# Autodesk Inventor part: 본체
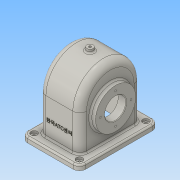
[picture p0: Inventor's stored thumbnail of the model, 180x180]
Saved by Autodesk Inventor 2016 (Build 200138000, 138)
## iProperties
Created: 2018-08
Part Number: 본체
Material: 알루미늄 6061
Document SubType Name: Modeling
Designer: Administrator
Density: 2.7 g/cm^3
Appearance: 강철
Mass: 1092.39 g
Surface Area: 1180.22 cm^2
Volume: 404.587 cm^3
Author: Administrator
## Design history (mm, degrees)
sketch "스케치1"
  geometry: L1 (-55, -75)-(55, -75); L2 (55, -75)-(55, 75); L3 (55, 75)-(-55, 75); L4 (-55, 75)-(-55, -75); L5 (-55, -75)-(55, 75); L6 (55, -75)-(-55, 75); 1 further point
  constraints: 12 end point, 2 midpoint, 2 parallel, 1 horizontal, 1 perpendicular
  dimensions: "d0" = 110 distance of L3.end L2.end; "d1" = 150 distance of L2.end L1.end
extrude "돌출1" new body sketch "스케치1" distance "d2" = 10; taper "d3" = 0 deg
sketch "스케치2"
  geometry: L1 (0, 0)-(-58, 0); L2 (-58, 0)-(-58, 78); L3 (-58, 78)-(0, 78); L4 (0, 78)-(0, 0); L5 (58, 78)-(0, 78); L6 (58, 0)-(58, 78); L7 (0, 0)-(58, 0); A1 r 58 centre (0, 78) between (58, 78) and (-58, 78)
  constraints: 14 end point, 2 parallel, 2 point on circle, 2 symmetric about line, 1 centre point, 1 coincident, 1 horizontal, 1 perpendicular
  dimensions: "d4" = 78 distance of L6.start L5.start; "d5" = 58 radius of A1
extrude "돌출2" join sketch "스케치2" stored distance "d6" = 77; taper "d7" = 0 deg
sketch "스케치3"
  geometry: L1 (0, 0)-(-52, 0); L2 (-52, 0)-(-52, 78); L3 (-52, 78)-(0, 78); L4 (0, 78)-(0, 0); L5 (52, 78)-(0, 78); L6 (52, 0)-(52, 78); L7 (0, 0)-(52, 0); L8 (58, 78)-(58, 10) reference; A1 r 58 centre (0, 78) between (58, 78) and (-58, 78) reference; A2 r 52 centre (0, 78) between (52, 78) and (-52, 78)
  constraints: 14 end point, 2 parallel, 2 point on circle, 1 centre point, 1 horizontal, 1 perpendicular, 1 symmetric about line
  dimensions: "d8" = 6 radial gap between concentric circles of A1 A2; "d9" = 52 radius of A2 (derived); "d10" = 6 distance between parallel lines of L8 L6
extrude "돌출3" cut sketch "스케치3" stored distance "d11" = 67; taper "d12" = 0 deg
sketch "스케치4"
  geometry: L1 (96.719, 65)-(-83.201, 65); L2 (-33.5, 0)-(33.5, 0) reference; L3 (-33.5, 65)-(-48.5, 65); L4 (-48.5, 65)-(-48.5, 103); L5 (-48.5, 103)-(-33.5, 103); L6 (-33.5, 103)-(-33.5, 65); L7 (-33.5, 130)-(-33.5, 78) reference; L8 (19.5, 65)-(19.5, 93); L9 (19.5, 93)-(33.5, 104.747); L10 (33.5, 104.747)-(38.5, 104.747); L11 (38.5, 78)-(38.5, 136) reference; L12 (38.5, 104.747)-(38.5, 103); L13 (38.5, 103)-(43.5, 103); L14 (43.5, 103)-(43.5, 65); L15 (43.5, 65)-(19.5, 65); 1 further point
  constraints: 24 end point, 5 point on line, 3 horizontal, 3 perpendicular, 2 collinear, 2 parallel, 1 vertical
  dimensions: "d13" = 65 distance between parallel lines of L2 L1; "d14" = 76 diameter of L5 L1; "d15" = 50 deg angle of L8 L9; "d16" = 5 distance of L9.end L10.end; "d17" = 56 diameter of L8.end L1; "d18" = 76 diameter of L13 L1; "d19" = 5 distance between parallel lines of L12 L14; "d20" = 87 distance between parallel lines of L4 L11; "d21" = 24 distance between parallel lines of L8 L14
revolve "회전1" sketch "스케치4" stored, may be unused: angle "d22" = 90 deg
sketch "스케치5"
  geometry: C1 r 38 at (0, 0) reference; C2 r 20 at (0, 0); 1 further point
  constraints: 1 centre point
  dimensions: "d23" = 40 diameter of C2
extrude "돌출4" cut sketch "스케치5" stored distance "d24" = 67; taper "d25" = 0 deg
sketch "스케치6" dims "d26" = 58
  geometry: L1 (0, 0)-(-29, 0); C1 r 38 at (0, 0) reference; 2 further points
  constraints: 2 end point, 1 coincident, 1 horizontal, 1 horizontal alignment, 2 other
hole "구멍1" sketch "스케치6" at (-29, 0) diameter "d27" = 3.242; stored, may be unused: countersink angle "d31" = 90 deg, drill point angle "d33" = 118 deg; dims "d28" = 8, "d29" = 4, "d30" = 2, "d32" = 10
node "작업 평면1"
sketch "스케치7"
  geometry: L1 (48.5, 38)-(48.5, -38) reference; L2 (-43.5, 1.621)-(-38.5, 1.621) reference; L3 (48.5, 1.621)-(48.5, -1.621) reference; L4 (-38.5, 58)-(-38.5, -58) reference; L5 (55, 75)-(-55, 75) reference; C1 r 6 at (0, 0); 1 further point
  constraints: 1 centre point
  dimensions: "d39" = 12 diameter of C1; "d103" = 38.5 distance from line of C1.centre L4; "d104" = 75 distance from line of L5 C1.centre
fillet "모깎기1" dims "d51" = 13
fillet "모깎기2" dims "d52" = 8
chamfer "모따기1" distance "d53" = 1; stored, may be unused: second distance "d54" = 2, angle "d55" = 45 deg
chamfer "모따기2" distance "d56" = 1; stored, may be unused: second distance "d57" = 2, angle "d58" = 45 deg
fillet "모깎기3" dims "d59" = 3
fillet "모깎기4" dims "d60" = 12
fillet "모깎기5" dims "d61" = 3
fillet "모깎기6" dims "d62" = 3
sketch "스케치8"
  geometry: L1 (-17.5, -78)-(68.5, -78) reference; L2 (-13, 0)-(-13, -65) reference; 2 further points
  constraints: 1 other
  dimensions: "d63" = 40 distance from line of L1 point (25.5, -38); "d64" = 38.5 distance from line of point (25.5, -38) L2
feature "엠보싱1" sketch "스케치8" dims "d0" = 110, "d1" = 150, "d4" = 78, "d65" = 0.5, "d66" = 0
hole "구멍3" diameter "d69" = 5; stored, may be unused: countersink angle "d73" = 90 deg, drill point angle "d75" = 118 deg; dims "d67" = 10, "d68" = 10, "d70" = 6, "d71" = 12, "d72" = 4, "d74" = 8
hole "구멍4" diameter "d78" = 5; stored, may be unused: countersink angle "d82" = 90 deg, drill point angle "d84" = 118 deg; dims "d76" = 10, "d77" = 10, "d79" = 6, "d80" = 12, "d81" = 4, "d83" = 8
hole "구멍5" diameter "d87" = 5; stored, may be unused: countersink angle "d91" = 90 deg, drill point angle "d93" = 118 deg; dims "d85" = 10, "d86" = 10, "d88" = 6, "d89" = 12, "d90" = 4, "d92" = 8
hole "구멍6" diameter "d96" = 5; stored, may be unused: countersink angle "d100" = 90 deg, drill point angle "d102" = 118 deg; dims "d94" = 10, "d95" = 10, "d97" = 6, "d98" = 12, "d99" = 4, "d101" = 8
sketch "스케치9" dims "d105" = 58
  geometry: L1 (0, 0)-(29, 0); C1 r 38 at (0, 0) reference; 2 further points
  constraints: 2 end point, 1 coincident, 1 horizontal, 1 horizontal alignment, 2 other
hole "구멍7" sketch "스케치9" at (29, 0) diameter "d106" = 3.242; stored, may be unused: countersink angle "d110" = 90 deg, drill point angle "d112" = 118 deg; dims "d107" = 8, "d108" = 12, "d109" = 4, "d111" = 10
extrude "돌출6" join sketch "스케치7" stored distance "d116" = 10; taper "d117" = 5 deg
fillet "모깎기7" dims "d118" = 3
hole "구멍8" diameter "d121" = 4.459; stored, may be unused: countersink angle "d125" = 90 deg, drill point angle "d127" = 118 deg; dims "d119" = 10, "d120" = 10, "d122" = 10, "d123" = 12, "d124" = 4, "d126" = 12.8
node "솔리드1"
pattern_circular "원형 패턴1" dims angle "d35" = 360 deg
pattern_circular "원형 패턴2" dims angle "d114" = 360 deg
other parameters: "d37" = 142
